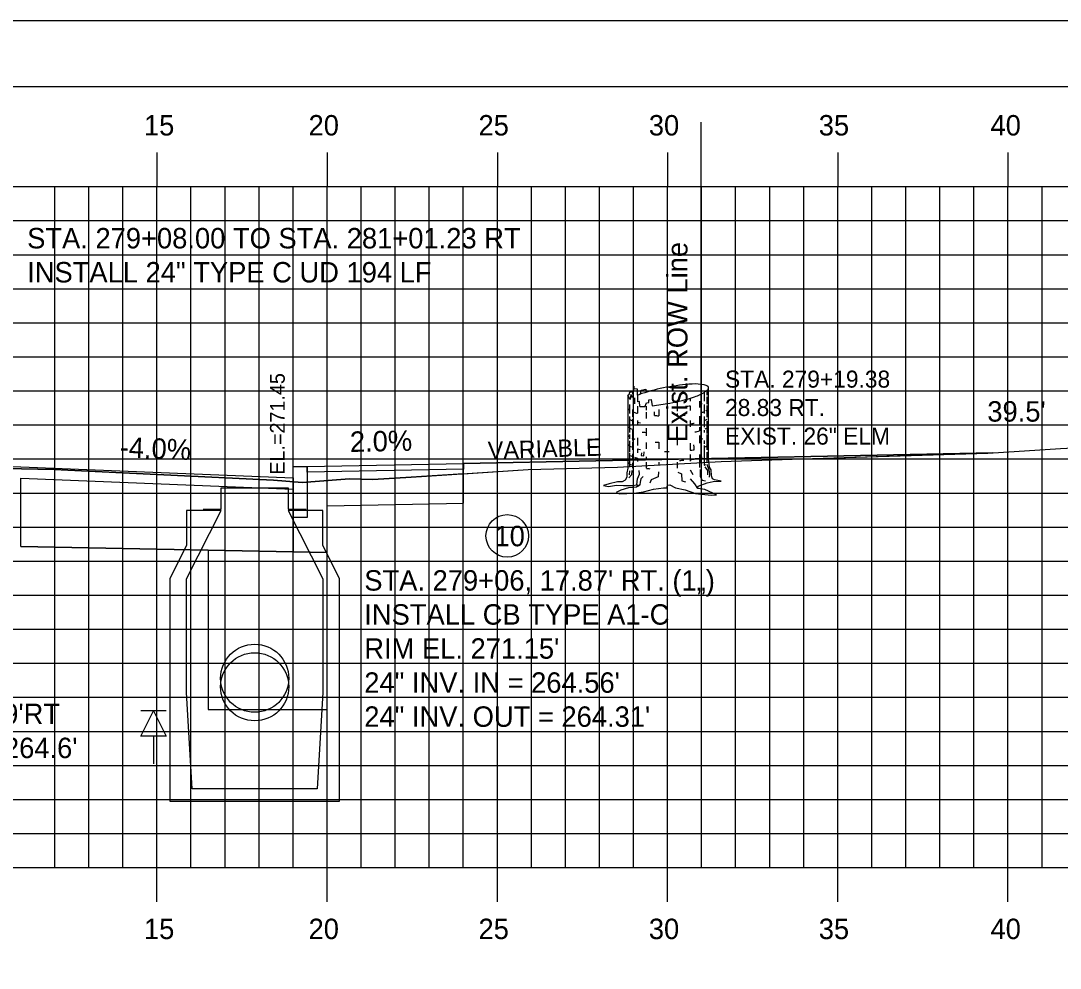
# Model space of a CAD drawing. Extents: x 854676 to 854846, y 366268 to 366378.
# Drawn here: x 854770.11 to 854800.64, y 366350.35 to 366378.18 of the extents above; entities that cross this region are included whole.
import ezdxf

# ---------------------------------------------------------------- set-up
doc = ezdxf.new("R2010")
doc.units = 0
for name, color, linetype in [('ANNOTATION', 7, 'Continuous'), ('BORDER', 7, 'Continuous'), ('D_Curb_Type1_Rt', 7, 'Continuous'), ('D_Curb_Type_1_Rt', 7, 'Continuous'), ('D_Drainage_CB_TypeA1-B1', 7, 'Continuous'), ('D_Drainage_Text', 7, 'Continuous'), ('D_Roadway_Edge_Shoulder', 7, 'Continuous'), ('D_Roadway_FinishedGrade', 7, 'Continuous'), ('D_Roadway_Sidewalks_Paved', 7, 'Continuous'), ('D_Roadway_SubGrade', 7, 'Continuous'), ('D_Text_Monospaced', 7, 'Continuous'), ('D_Text_Standard', 7, 'Continuous'), ('E_ROW_Line', 7, 'Continuous'), ('H_V ANNOTATION', 7, 'Continuous'), ('JUNK COM EXC', 7, 'Continuous'), ('JUNK FILL', 7, 'Continuous'), ('junk strct exc', 7, 'Continuous'), ('MAJOR', 7, 'Continuous'), ('MINOR', 7, 'Continuous'), ('PDRAIN', 7, 'Continuous'), ('PLOT BOUNDARY', 7, 'Continuous'), ('ROCKS', 7, 'Continuous'), ('S_Roadway_Centerline', 7, 'Continuous'), ('S_Trees_Decid_Pay', 7, 'Continuous')]:
    doc.layers.add(name, color=color, linetype=linetype)

msp = doc.modelspace()

# ---------------------------------------------------------------- linework, layer by layer
at = {"layer": 'BORDER'}
msp.add_line((854844.107, 366376.236), (854684.107, 366376.236), dxfattribs=at)
at = {"layer": 'D_Curb_Type1_Rt'}
msp.add_line((854778.106, 366364.755), (854778.106, 366365.088), dxfattribs=at)
at = {"layer": 'D_Curb_Type_1_Rt'}
msp.add_lwpolyline([(854778.523, 366365.088), (854778.523, 366363.588), (854778.106, 366363.588), (854778.106, 366365.088)], close=True, dxfattribs=at)
at = {"layer": 'D_Drainage_CB_TypeA1-B1'}
for p, q in [((854774.975, 366363.794), (854774.975, 366362.777)), ((854774.975, 366361.793), (854775.992, 366363.794)), ((854775.992, 366363.794), (854774.975, 366363.794)), ((854778.978, 366363.794), (854777.961, 366363.794)), ((854777.961, 366363.794), (854778.978, 366361.793)), ((854778.978, 366362.777), (854778.978, 366363.794)), ((854774.975, 366362.777), (854774.483, 366361.793)), ((854779.47, 366361.793), (854778.978, 366362.777)), ((854774.483, 366361.793), (854774.483, 366355.258)), ((854774.975, 366358.446), (854774.975, 366361.793)), ((854778.978, 366361.793), (854778.978, 366358.446)), ((854779.47, 366355.258), (854779.47, 366361.793)), ((854775.139, 366355.619), (854774.975, 366358.446)), ((854778.978, 366358.446), (854778.814, 366355.619)), ((854778.814, 366355.619), (854775.139, 366355.619)), ((854774.483, 366355.258), (854779.47, 366355.258))]:
    msp.add_line(p, q, dxfattribs=at)
msp.add_lwpolyline([(854775.467, 366363.836), (854775.992, 366363.836), (854775.992, 366364.459), (854777.961, 366364.459), (854777.961, 366363.836), (854778.486, 366363.836)], dxfattribs=at)
at = {"layer": 'D_Drainage_Text'}
msp.add_circle((854784.397, 366363.049), 0.625, dxfattribs=at)
at = {"layer": 'D_Roadway_Edge_Shoulder'}
msp.add_line((854778.106, 366364.755), (854778.107, 366364.422), dxfattribs=at)
msp.add_lwpolyline([(854740.106, 366364.866), (854748.106, 366365.186), (854759.106, 366365.296), (854770.106, 366365.076), (854778.106, 366364.755)], dxfattribs=at)
at = {"layer": 'D_Roadway_FinishedGrade'}
msp.add_lwpolyline([(854783.112, 366365.18), (854798.656, 366365.491)], dxfattribs=at)
at = {"layer": 'D_Roadway_Sidewalks_Paved'}
msp.add_lwpolyline([(854778.523, 366365.088), (854783.112, 366365.18), (854783.112, 366365.013), (854778.523, 366364.921)], close=True, dxfattribs=at)
at = {"layer": 'D_Roadway_SubGrade'}
msp.add_line((854778.107, 366362.582), (854779.106, 366362.562), dxfattribs=at)
msp.add_lwpolyline([(854779.11, 366362.562), (854779.11, 366363.933), (854783.112, 366364.013), (854783.112, 366365.013)], dxfattribs=at)
msp.add_lwpolyline([(854770.106, 366364.742), (854778.107, 366364.422), (854778.107, 366362.582), (854770.106, 366362.742)], close=True, dxfattribs=at)
at = {"layer": 'E_ROW_Line'}
msp.add_line((854790.09, 366365.198), (854790.09, 366375.198), dxfattribs=at)
at = {"layer": 'JUNK COM EXC'}
msp.add_lwpolyline([(854770.106, 366362.742), (854779.106, 366362.562), (854779.11, 366363.933), (854783.112, 366364.013), (854783.112, 366364.877), (854781.576, 366364.775), (854780.446, 366364.709), (854779.762, 366364.729), (854778.629, 366364.634), (854778.369, 366364.622), (854777.534, 366364.686), (854771.088, 366364.995), (854760.071, 366365.226)], dxfattribs=at)
at = {"layer": 'JUNK FILL'}
msp.add_lwpolyline([(854783.106, 366365.18), (854783.106, 366364.877), (854785.006, 366365.003), (854787.636, 366365.067), (854790.678, 366365.23), (854793.359, 366365.326), (854798.656, 366365.491), (854783.112, 366365.18)], close=True, dxfattribs=at)
at = {"layer": 'junk strct exc'}
msp.add_lwpolyline([(854775.606, 366362.632), (854775.61, 366357.949), (854779.11, 366357.949), (854779.106, 366362.562)], close=True, dxfattribs=at)
at = {"layer": 'MAJOR'}
for p, q in [((854774.106, 366374.311), (854774.106, 366373.309)), ((854779.106, 366374.311), (854779.106, 366373.309)), ((854784.106, 366374.311), (854784.106, 366373.309)), ((854789.106, 366374.311), (854789.106, 366373.309)), ((854794.106, 366374.311), (854794.106, 366373.309)), ((854799.106, 366374.311), (854799.106, 366373.309)), ((854689.106, 366373.309), (854829.106, 366373.309)), ((854689.106, 366373.309), (854829.106, 366373.309)), ((854774.106, 366353.309), (854774.106, 366373.309)), ((854779.106, 366353.309), (854779.106, 366373.309)), ((854784.106, 366353.309), (854784.106, 366373.309)), ((854789.106, 366353.309), (854789.106, 366373.309)), ((854794.106, 366353.309), (854794.106, 366373.309)), ((854799.106, 366353.309), (854799.106, 366373.309)), ((854689.106, 366368.309), (854829.106, 366368.309)), ((854689.106, 366363.309), (854829.106, 366363.309)), ((854689.106, 366358.309), (854829.106, 366358.309)), ((854689.106, 366353.309), (854829.106, 366353.309)), ((854689.106, 366353.309), (854829.106, 366353.309)), ((854774.106, 366352.307), (854774.106, 366353.309)), ((854779.106, 366352.307), (854779.106, 366353.309)), ((854784.106, 366352.307), (854784.106, 366353.309)), ((854789.106, 366352.307), (854789.106, 366353.309)), ((854794.106, 366352.307), (854794.106, 366353.309)), ((854799.106, 366352.307), (854799.106, 366353.309))]:
    msp.add_line(p, q, dxfattribs=at)
at = {"layer": 'MINOR'}
for p, q in [((854771.106, 366353.309), (854771.106, 366373.309)), ((854772.106, 366353.309), (854772.106, 366373.309)), ((854773.106, 366353.309), (854773.106, 366373.309)), ((854775.106, 366353.309), (854775.106, 366373.309)), ((854776.106, 366353.309), (854776.106, 366373.309)), ((854777.106, 366353.309), (854777.106, 366373.309)), ((854778.106, 366353.309), (854778.106, 366373.309)), ((854780.106, 366353.309), (854780.106, 366373.309)), ((854781.106, 366353.309), (854781.106, 366373.309)), ((854782.106, 366353.309), (854782.106, 366373.309)), ((854783.106, 366353.309), (854783.106, 366373.309)), ((854785.106, 366353.309), (854785.106, 366373.309)), ((854786.106, 366353.309), (854786.106, 366373.309)), ((854787.106, 366353.309), (854787.106, 366373.309)), ((854788.106, 366353.309), (854788.106, 366373.309)), ((854790.106, 366353.309), (854790.106, 366373.309)), ((854791.106, 366353.309), (854791.106, 366373.309)), ((854792.106, 366353.309), (854792.106, 366373.309)), ((854793.106, 366353.309), (854793.106, 366373.309)), ((854795.106, 366353.309), (854795.106, 366373.309)), ((854796.106, 366353.309), (854796.106, 366373.309)), ((854797.106, 366353.309), (854797.106, 366373.309)), ((854798.106, 366353.309), (854798.106, 366373.309)), ((854800.106, 366353.309), (854800.106, 366373.309)), ((854689.106, 366372.309), (854829.106, 366372.309)), ((854689.106, 366371.309), (854829.106, 366371.309)), ((854689.106, 366370.309), (854829.106, 366370.309)), ((854689.106, 366369.309), (854829.106, 366369.309)), ((854689.106, 366367.309), (854829.106, 366367.309)), ((854689.106, 366366.309), (854829.106, 366366.309)), ((854689.106, 366365.309), (854829.106, 366365.309)), ((854689.106, 366364.309), (854829.106, 366364.309)), ((854689.106, 366362.309), (854829.106, 366362.309)), ((854689.106, 366361.309), (854829.106, 366361.309)), ((854689.106, 366360.309), (854829.106, 366360.309)), ((854689.106, 366359.309), (854829.106, 366359.309)), ((854689.106, 366357.309), (854829.106, 366357.309)), ((854689.106, 366356.309), (854829.106, 366356.309)), ((854689.106, 366355.309), (854829.106, 366355.309)), ((854689.106, 366354.309), (854829.106, 366354.309))]:
    msp.add_line(p, q, dxfattribs=at)
at = {"layer": 'PDRAIN'}
for centre in [(854776.977, 366358.869), (854776.977, 366358.619)]:
    msp.add_circle(centre, 1, dxfattribs=at)
at = {"layer": 'PLOT BOUNDARY'}
msp.add_lwpolyline([(854676.013, 366268.177), (854846.013, 366268.177), (854846.013, 366378.177), (854676.013, 366378.177)], close=True, dxfattribs=at)
at = {"layer": 'ROCKS'}
for p, q in [((854774.375, 366357.909), (854773.637, 366357.909)), ((854774.006, 366357.171), (854774.006, 366356.356))]:
    msp.add_line(p, q, dxfattribs=at)
msp.add_lwpolyline([(854774.006, 366357.909), (854774.375, 366357.171), (854773.637, 366357.171)], close=True, dxfattribs=at)
at = {"layer": 'S_Roadway_Centerline'}
msp.add_lwpolyline([(854760.071, 366365.226), (854771.088, 366364.995), (854777.534, 366364.686), (854778.369, 366364.622), (854778.629, 366364.634), (854779.762, 366364.729), (854780.446, 366364.709), (854781.576, 366364.775), (854785.006, 366365.003), (854787.636, 366365.067), (854790.678, 366365.23), (854793.359, 366365.326), (854798.518, 366365.484), (854799.286, 366365.525), (854800.647, 366365.62), (854803.663, 366365.778), (854804.946, 366365.832), (854807.983, 366365.97), (854814.583, 366366.102), (854822.139, 366366.02), (854822.216, 366366.887)], dxfattribs=at)
at = {"layer": 'S_Trees_Decid_Pay'}
for p, q in [((854790.179, 366367.263), (854790.179, 366367.01)), ((854790.259, 366367.307), (854790.259, 366367.187)), ((854788.134, 366367.104), (854788.134, 366366.93)), ((854789.391, 366366.995), (854789.391, 366366.715)), ((854789.774, 366367.096), (854789.774, 366367.01)), ((854790.046, 366367.01), (854790.046, 366366.818)), ((854790.259, 366367.135), (854790.259, 366366.921)), ((854787.985, 366366.904), (854787.985, 366366.649)), ((854788.071, 366366.758), (854788.071, 366366.546)), ((854788.219, 366366.855), (854788.219, 366366.651)), ((854788.48, 366366.857), (854788.48, 366366.738)), ((854788.48, 366366.686), (854788.48, 366366.501)), ((854788.718, 366366.586), (854788.724, 366366.693)), ((854788.845, 366366.758), (854788.845, 366366.578)), ((854789.391, 366366.649), (854789.391, 366366.546)), ((854789.774, 366366.868), (854789.774, 366366.729)), ((854790.179, 366366.913), (854790.179, 366366.649)), ((854790.259, 366366.876), (854790.259, 366366.538)), ((854787.985, 366366.552), (854787.985, 366366.083)), ((854788.071, 366366.481), (854788.071, 366366.332)), ((854788.219, 366366.443), (854788.219, 366366.289)), ((854789.774, 366366.443), (854789.774, 366366.252)), ((854790.046, 366366.567), (854790.046, 366366.289)), ((854790.179, 366366.552), (854790.179, 366366.244)), ((854790.259, 366366.421), (854790.259, 366366.06)), ((854787.985, 366366.032), (854787.985, 366365.898)), ((854788.071, 366366.155), (854788.071, 366365.855)), ((854788.48, 366366.215), (854788.48, 366365.987)), ((854790.046, 366366.244), (854790.046, 366366.135)), ((854790.179, 366366.155), (854790.179, 366366.089)), ((854790.259, 366366.023), (854790.259, 366365.575)), ((854787.985, 366365.84), (854787.985, 366365.515)), ((854788.071, 366365.817), (854788.071, 366365.575)), ((854788.219, 366365.926), (854788.219, 366365.706)), ((854788.48, 366365.788), (854788.48, 366365.603)), ((854788.845, 366365.8), (854788.845, 366365.603)), ((854789.391, 366365.935), (854789.391, 366365.714)), ((854789.774, 366365.772), (854789.774, 366365.564)), ((854790.046, 366366), (854790.046, 366365.772)), ((854790.179, 366365.855), (854790.179, 366365.758)), ((854787.985, 366365.486), (854787.985, 366365.066)), ((854788.071, 366365.464), (854788.071, 366365.323)), ((854788.219, 366365.607), (854788.219, 366365.486)), ((854789.774, 366365.443), (854789.774, 366365.243)), ((854790.046, 366365.443), (854790.046, 366365.059)), ((854790.179, 366365.706), (854790.179, 366365.346)), ((854790.259, 366365.509), (854790.259, 366365.227)), ((854788.071, 366365.191), (854788.071, 366365.035)), ((854788.219, 366365.335), (854788.219, 366365.237)), ((854788.48, 366365.369), (854788.48, 366365.292)), ((854788.48, 366365.214), (854788.48, 366365.041)), ((854788.845, 366365.22), (854788.845, 366365.117)), ((854789.391, 366365.214), (854789.391, 366365.041)), ((854790.179, 366365.294), (854790.179, 366365.128)), ((854787.988, 366364.963), (854787.974, 366364.846)), ((854789.769, 366364.986), (854789.85, 366364.854))]:
    msp.add_line(p, q, dxfattribs=at)
for points in [[(854787.934, 366367.178), (854787.934, 366365.041), (854787.914, 366364.899), (854787.908, 366364.773), (854787.865, 366364.687), (854787.772, 366364.638), (854787.636, 366364.638), (854787.393, 366364.582), (854787.226, 366364.533), (854787.369, 366364.502), (854787.605, 366364.539), (854787.815, 366364.527), (854788.077, 366364.533), (854788.201, 366364.551), (854788.231, 366364.508), (854788.293, 366364.551), (854788.194, 366364.483), (854787.959, 366364.458), (854787.729, 366364.397), (854787.599, 366364.327), (854787.698, 366364.283), (854788.12, 366364.302), (854788.398, 366364.346), (854788.697, 366364.422), (854788.983, 366364.458), (854789.088, 366364.458), (854789.106, 366364.539), (854789.174, 366364.545), (854789.341, 366364.458), (854789.627, 366364.403), (854789.926, 366364.296), (854790.385, 366364.246), (854790.539, 366364.259), (854790.197, 366364.409), (854789.994, 366364.44), (854790.006, 366364.514), (854790.266, 366364.613), (854790.441, 366364.644), (854790.682, 366364.656), (854790.483, 366364.693), (854790.422, 366364.73), (854790.397, 366364.817), (854790.385, 366364.986), (854790.34, 366365.072), (854790.311, 366365.313), (854790.311, 366367.399)], [(854788.29, 366366.851), (854788.283, 366366.995), (854788.237, 366366.987), (854788.223, 366367.362), (854788.128, 366367.37), (854788.114, 366367.45), (854788.077, 366367.113), (854788.031, 366367.207), (854788.011, 366367.053), (854787.934, 366367.178), (854787.94, 366366.989)], [(854787.934, 366367.178), (854787.98, 366367.201), (854788.002, 366367.267), (854788.054, 366367.29), (854788.088, 366367.215)], [(854788.313, 366367.217), (854788.334, 366367.325), (854788.466, 366367.355), (854788.473, 366367.267)], [(854788.452, 366366.855), (854788.489, 366366.958), (854788.554, 366366.964), (854788.554, 366367.046), (854788.628, 366367.053), (854788.653, 366366.872)], [(854789.888, 366365.578), (854789.886, 366365.655), (854789.878, 366365.721)], [(854788.342, 366365.486), (854788.334, 366365.412), (854788.408, 366365.406), (854788.422, 366365.523)], [(854790.261, 366365.155), (854790.321, 366364.994), (854790.335, 366364.869), (854790.327, 366364.771)], [(854788.054, 366364.971), (854788.048, 366364.846), (854787.966, 366364.751)], [(854788.201, 366364.551), (854788.219, 366364.73), (854788.281, 366364.867), (854788.274, 366364.967)], [(854788.843, 366364.934), (854788.826, 366364.78), (854788.628, 366364.699), (854788.583, 366364.596)], [(854789.409, 366364.926), (854789.512, 366364.874), (854789.526, 366364.668), (854789.629, 366364.64)], [(854790.063, 366365), (854790.063, 366364.794), (854790.121, 366364.685), (854790.218, 366364.668)], [(854790.204, 366365.074), (854790.275, 366364.971), (854790.275, 366364.846)], [(854788.392, 366364.798), (854788.317, 366364.73), (854788.299, 366364.632), (854788.293, 366364.551)], [(854789.994, 366364.44), (854789.907, 366364.582), (854789.775, 366364.724)]]:
    msp.add_lwpolyline(points, dxfattribs=at)
for centre, radius, start, end in [((854790.224, 366361.397), 6.126, 100.7779, 107.8613), ((854790.224, 366361.397), 6.126, 93.6944, 100.7779), ((854789.913, 366366.213), 1.299, 78.2779, 93.6944), ((854789.502, 366368.372), 1.299, 287.8613, 303.2779), ((854790.08, 366367.016), 0.48, 69.9843, 78.2779), ((854789.952, 366367.687), 0.48, 303.2779, 311.5714), ((854790.188, 366367.313), 0.164, 55.7779, 69.9843), ((854790.161, 366367.451), 0.164, 311.5714, 325.7779), ((854790.22, 366367.36), 0.107, 45.9547, 55.7779), ((854790.249, 366367.39), 0.0645, 33.2779, 45.9547), ((854790.208, 366367.419), 0.107, 325.7779, 335.6011), ((854790.258, 366367.396), 0.0544, 22.46, 33.2779), ((854790.247, 366367.401), 0.0645, 335.6011, 348.2779), ((854790.265, 366367.399), 0.0467, 10.7779, 22.46), ((854790.257, 366367.399), 0.0544, 348.2779, 359.0957), ((854790.265, 366367.399), 0.0467, 359.0957, 10.7779), ((854788.744, 366365.991), 1.299, 107.8613, 113.3069), ((854788.022, 366372.966), 6.126, 275.9147, 280.7779), ((854788.022, 366372.966), 6.126, 280.7779, 287.8613), ((854789.7, 366368.161), 1.292, 285.5651, 289.0916), ((854790.172, 366367.142), 0.166, 301.67, 315), ((854790.212, 366367.101), 0.109, 315, 324.8263), ((854790.248, 366367.076), 0.0657, 324.8263, 337.5), ((854790.257, 366367.072), 0.0554, 337.5, 348.3185), ((854787.982, 366366.81), 0.0476, 180, 191.6815), ((854787.99, 366366.811), 0.0554, 191.6815, 202.5), ((854787.999, 366366.815), 0.0657, 202.5, 215.1737), ((854788.035, 366366.84), 0.109, 215.1737, 225), ((854788.075, 366366.881), 0.166, 225, 239.1924), ((854788.547, 366367.9), 1.292, 250.6119, 255.2856), ((854788.333, 366368.149), 1.299, 268.1289, 273.6944), ((854788.022, 366372.966), 6.126, 273.6944, 274.0246), ((854789.124, 366372.749), 5.916, 274.9515, 276.3087), ((854789.699, 366367.9), 1.292, 288.0829, 292.5), ((854790.008, 366367.154), 0.484, 297.4162, 300.8076), ((854790.171, 366366.881), 0.166, 300.8076, 315), ((854790.211, 366366.84), 0.109, 315, 324.8263), ((854790.247, 366366.815), 0.0657, 324.8263, 337.5), ((854790.256, 366366.811), 0.0554, 337.5, 348.3185), ((854788.075, 366366.617), 0.166, 237.0378, 239.1924), ((854788.238, 366366.89), 0.484, 239.1924, 247.5), ((854788.547, 366367.637), 1.292, 247.5, 248.3537), ((854788.547, 366367.637), 1.292, 255.2856, 259.2632), ((854789.123, 366372.488), 5.916, 266.0776, 267.3043), ((854789.123, 366372.488), 5.916, 273.5382, 274.8924), ((854789.123, 366372.225), 5.916, 276.3184, 277.1546), ((854789.699, 366367.637), 1.292, 277.1546, 278.3662), ((854789.699, 366367.637), 1.292, 291.8071, 292.5), ((854790.008, 366366.89), 0.484, 292.5, 300.8076), ((854790.171, 366366.617), 0.166, 300.8076, 301.6001), ((854787.982, 366366.289), 0.0476, 180, 191.6815), ((854787.982, 366366.032), 0.0476, 180, 191.6815), ((854787.99, 366366.291), 0.0554, 191.6815, 202.5), ((854787.999, 366366.294), 0.0657, 202.5, 215.1737), ((854788.035, 366366.319), 0.109, 215.1737, 225), ((854788.075, 366366.36), 0.166, 225, 239.1924), ((854788.238, 366366.633), 0.484, 239.1924, 245.7725), ((854788.547, 366367.379), 1.292, 247.5, 248.4842), ((854788.547, 366367.379), 1.292, 261.8726, 262.8454), ((854789.123, 366371.967), 5.916, 262.8454, 263.7595), ((854789.123, 366372.225), 5.916, 270.1162, 271.7708), ((854789.699, 366367.379), 1.292, 279.2565, 285.6105), ((854790.008, 366366.633), 0.484, 294.6372, 300.8076), ((854790.171, 366366.36), 0.166, 300.8076, 315), ((854790.211, 366366.319), 0.109, 315, 324.8263), ((854790.247, 366366.294), 0.0657, 324.8263, 337.5), ((854790.256, 366366.291), 0.0554, 337.5, 348.3185), ((854787.982, 366365.766), 0.0476, 180, 191.6815), ((854787.99, 366366.033), 0.0554, 191.6815, 202.5), ((854787.99, 366365.768), 0.0554, 191.6815, 202.5), ((854787.999, 366366.037), 0.0657, 202.5, 215.1737), ((854787.999, 366365.771), 0.0657, 202.5, 215.1737), ((854788.035, 366366.062), 0.109, 215.1737, 225), ((854788.035, 366365.796), 0.109, 215.1737, 225), ((854788.075, 366366.103), 0.166, 225, 239.1924), ((854788.075, 366365.837), 0.166, 225, 239.1924), ((854788.547, 366367.122), 1.292, 247.5, 251.799), ((854789.123, 366371.71), 5.916, 266.2721, 267.3043), ((854789.699, 366367.122), 1.292, 285.6105, 290.1001), ((854790.171, 366366.103), 0.166, 302.0694, 315), ((854790.211, 366366.062), 0.109, 315, 324.8263), ((854790.247, 366366.037), 0.0657, 324.8263, 337.5), ((854790.256, 366366.033), 0.0554, 337.5, 348.3185), ((854790.256, 366365.768), 0.0554, 337.5, 348.3185), ((854788.238, 366366.11), 0.484, 239.1924, 247.5), ((854788.547, 366366.856), 1.292, 247.5, 248.3537), ((854788.547, 366366.856), 1.292, 255.2856, 259.2463), ((854789.123, 366371.444), 5.916, 268.9207, 270), ((854789.123, 366371.444), 5.916, 270, 270.2757), ((854789.123, 366371.444), 5.916, 276.3184, 277.1546), ((854789.699, 366366.856), 1.292, 277.1546, 278.3795), ((854790.008, 366366.11), 0.484, 292.5, 300.8076), ((854790.171, 366365.837), 0.166, 300.8076, 302.0694), ((854790.171, 366365.565), 0.166, 302.0694, 315), ((854790.211, 366365.525), 0.109, 315, 324.8263), ((854790.247, 366365.5), 0.0657, 324.8263, 337.5), ((854790.256, 366365.496), 0.0554, 337.5, 348.3185), ((854787.982, 366365.237), 0.0476, 180, 191.6815), ((854787.99, 366365.238), 0.0554, 191.6815, 202.5), ((854787.999, 366365.242), 0.0657, 202.5, 215.1737), ((854788.035, 366365.267), 0.109, 215.1737, 225), ((854788.075, 366365.308), 0.166, 225, 239.1924), ((854788.238, 366365.581), 0.484, 239.1924, 247.5), ((854788.238, 366365.838), 0.484, 242.734, 247.5), ((854788.547, 366366.327), 1.292, 247.5, 248.3537), ((854788.547, 366366.585), 1.292, 251.3664, 255.2856), ((854789.123, 366371.172), 5.916, 273.2637, 274.461), ((854789.123, 366371.172), 5.916, 276.3184, 277.1546), ((854789.699, 366366.585), 1.292, 277.1546, 278.3662), ((854789.699, 366366.585), 1.292, 285.6105, 289.1534), ((854789.708, 366366.331), 1.292, 291.3696, 292.0604), ((854790.008, 366365.581), 0.484, 292.5, 296.5499), ((854789.123, 366370.915), 5.916, 263.7831, 264.7656)]:
    msp.add_arc(centre, radius, start, end, dxfattribs=at)

# ---------------------------------------------------------------- texts
at = {"layer": 'ANNOTATION'}
for s, rotation, p in [('2.0%', 1.1485, (854779.78, 366365.514)), ('-4.0%', 357.7094, (854773.002, 366365.36))]:
    msp.add_text(s, height=0.6, rotation=rotation, dxfattribs=at).set_placement(p)
at = {"layer": 'D_Drainage_Text'}
for s, p in [('STA. 279+08.00 TO STA. 281+01.23 RT', (854770.294, 366371.493)), ('INSTALL 24" TYPE C UD 194 LF', (854770.294, 366370.493)), ("STA. 279+06, 17.87' RT. (1„)", (854780.197, 366361.443)), ('INSTALL CB TYPE A1-C', (854780.197, 366360.443)), ("RIM EL. 271.15'", (854780.197, 366359.443)), ('24" INV. IN = 264.56\'', (854780.197, 366358.443)), ('24" INV. OUT = 264.31\'', (854780.197, 366357.443))]:
    msp.add_text(s, height=0.6, dxfattribs=at).set_placement(p)
at = {"layer": 'D_Text_Monospaced'}
for s, height, p in [('STA. 279+19.38', 0.49998, (854790.794, 366367.404)), ('28.83 RT.', 0.5, (854790.794, 366366.57)), ('EXIST. 26" ELM', 0.49998, (854790.794, 366365.73))]:
    msp.add_text(s, height=height, dxfattribs=at).set_placement(p)
at = {"layer": 'D_Text_Standard'}
for s, height, rotation, p in [(' EL.=271.45', 0.4335, 90, (854777.861, 366364.687)), ('VARIABLE', 0.51, 1.7333, (854783.834, 366365.305))]:
    msp.add_text(s, height=height, rotation=rotation, dxfattribs=at).set_placement(p)
msp.add_text("39.5'", height=0.6, dxfattribs=at).set_placement((854798.499, 366366.406))
at = {"layer": 'E_ROW_Line'}
msp.add_text('Exist. ROW Line', height=0.6, rotation=90, dxfattribs=at).set_placement((854789.69, 366365.798))
at = {"layer": 'H_V ANNOTATION'}
for s, p in [('15', (854773.724, 366374.809)), ('20', (854778.56, 366374.809)), ('25', (854783.552, 366374.809)), ('30', (854788.555, 366374.809)), ('35', (854793.547, 366374.809)), ('40', (854798.592, 366374.809)), ('10', (854784.021, 366362.745)), ('15', (854773.724, 366351.209)), ('20', (854778.56, 366351.209)), ('25', (854783.552, 366351.209)), ('30', (854788.555, 366351.209)), ('35', (854793.547, 366351.209)), ('40', (854798.592, 366351.209))]:
    msp.add_text(s, height=0.6, dxfattribs=at).set_placement(p)
at = {"layer": 'ROCKS'}
for s, p in [("STA. 279+00, 14.9'RT", (854763.324, 366357.524)), ("APPROX. ELEV. 264.6'", (854763.324, 366356.524))]:
    msp.add_text(s, height=0.6, dxfattribs=at).set_placement(p)

doc.saveas('drawing.dxf')
